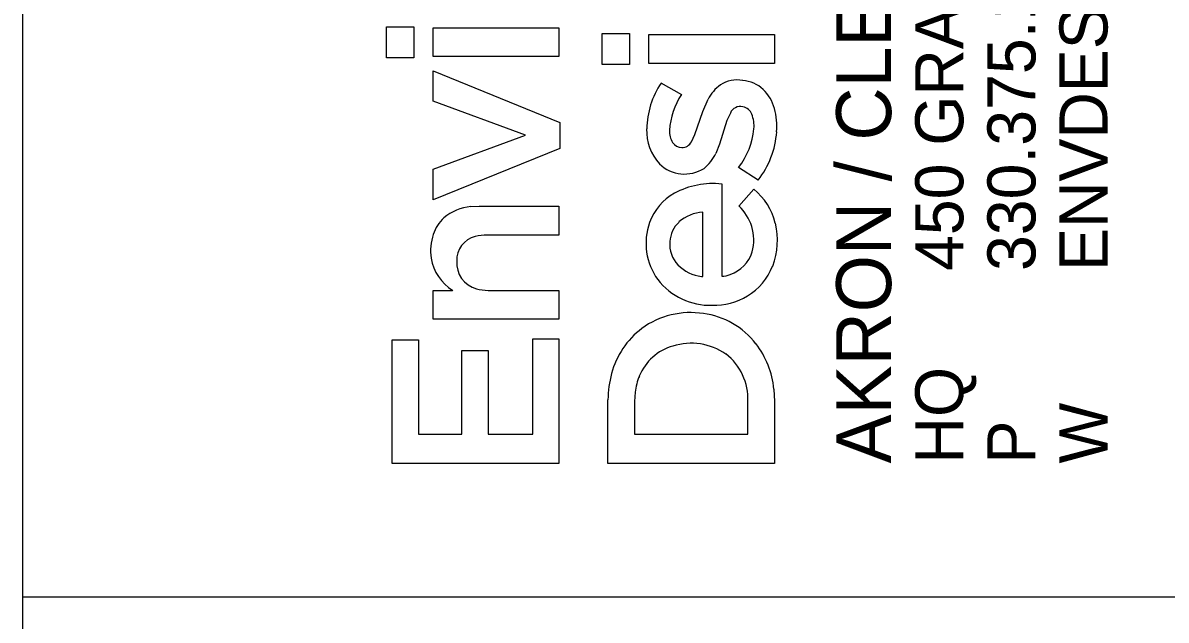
# Model space of a CAD drawing. Extents: x -0.4 to 34, y 0 to 22.
# Drawn here: x 32 to 33.185, y 2.476 to 3.094 of the extents above; entities that cross this region are included whole.
import ezdxf

# ---------------------------------------------------------------- set-up
doc = ezdxf.new("R2010")
doc.units = 0
doc.layers.add('SH_Border', color=7, linetype='Continuous')
doc.layers.add('SH_Data', color=7, linetype='Continuous')

msp = doc.modelspace()

# ---------------------------------------------------------------- linework, layer by layer
at = {"layer": 'SH_Border'}
for p, q in [((32, 0.5), (32, 21.5)), ((32, 2.5), (33.5, 2.5))]:
    msp.add_line(p, q, dxfattribs=at)
at = {"layer": 'SH_Data'}
for p, q in [((32.3771, 3.0582), (32.3771, 3.0903)), ((32.3771, 3.0903), (32.4054, 3.0903)), ((32.4054, 3.0903), (32.4054, 3.0582)), ((32.4254, 3.0594), (32.4254, 3.0893)), ((32.4254, 3.0893), (32.5557, 3.0893)), ((32.5557, 3.0893), (32.5557, 3.0594)), ((32.6005, 3.0511), (32.6005, 3.0832)), ((32.6005, 3.0832), (32.6289, 3.0832)), ((32.6289, 3.0832), (32.6289, 3.0511)), ((32.6489, 3.0523), (32.6489, 3.0822)), ((32.6489, 3.0822), (32.7792, 3.0822)), ((32.7792, 3.0822), (32.7792, 3.0523)), ((32.4054, 3.0582), (32.3771, 3.0582)), ((32.5557, 3.0594), (32.4254, 3.0594)), ((32.6289, 3.0511), (32.6005, 3.0511)), ((32.7792, 3.0523), (32.6489, 3.0523)), ((32.4254, 3.0133), (32.4254, 3.0446)), ((32.4254, 3.0446), (32.5567, 2.9913)), ((32.6615, 3.0321), (32.6827, 3.0203)), ((32.5212, 2.978), (32.4254, 3.0133)), ((32.7048, 3.0026), (32.7104, 3.0153)), ((32.6967, 2.9787), (32.7048, 3.0026)), ((32.7334, 3.001), (32.7298, 2.9933)), ((32.5567, 2.9913), (32.5567, 2.9644)), ((32.7298, 2.9933), (32.7221, 2.9688)), ((32.4254, 2.9429), (32.5212, 2.978)), ((32.693, 2.9712), (32.6967, 2.9787)), ((32.5567, 2.9644), (32.4254, 2.9109)), ((32.7221, 2.9688), (32.7182, 2.9592)), ((32.4254, 2.9109), (32.4254, 2.9429)), ((32.7621, 2.9314), (32.742, 2.9447)), ((32.7245, 2.9275), (32.7246, 2.8319)), ((32.7423, 2.9046), (32.7577, 2.922)), ((32.4644, 2.904), (32.4729, 2.9044)), ((32.4729, 2.9044), (32.5557, 2.9044)), ((32.5557, 2.9044), (32.5557, 2.8746)), ((32.7049, 2.8318), (32.7049, 2.8983)), ((32.5557, 2.8746), (32.4814, 2.8746)), ((32.7036, 2.8317), (32.7049, 2.8318)), ((32.4254, 2.7875), (32.4254, 2.8173)), ((32.4254, 2.8173), (32.4455, 2.8173)), ((32.4822, 2.8173), (32.5557, 2.8173)), ((32.5557, 2.8173), (32.5557, 2.7876)), ((32.5557, 2.7876), (32.4254, 2.7875)), ((32.383, 2.6379), (32.383, 2.766)), ((32.383, 2.766), (32.4101, 2.766)), ((32.4101, 2.766), (32.4101, 2.6683)), ((32.5286, 2.6683), (32.5286, 2.7672)), ((32.5286, 2.7672), (32.5557, 2.7672)), ((32.5557, 2.7672), (32.5557, 2.6379)), ((32.455, 2.6683), (32.455, 2.7549)), ((32.455, 2.7549), (32.4822, 2.7549)), ((32.4822, 2.7549), (32.4822, 2.6683)), ((32.7785, 2.715), (32.7792, 2.7021)), ((32.6064, 2.638), (32.6064, 2.704)), ((32.6347, 2.7118), (32.6341, 2.7023)), ((32.6341, 2.7023), (32.6341, 2.6684)), ((32.7515, 2.6683), (32.7515, 2.7024)), ((32.7792, 2.7021), (32.7792, 2.638)), ((32.4101, 2.6683), (32.455, 2.6683)), ((32.4822, 2.6683), (32.5286, 2.6683)), ((32.6341, 2.6684), (32.7515, 2.6683)), ((32.5557, 2.6379), (32.383, 2.6379)), ((32.7792, 2.638), (32.6064, 2.638))]:
    msp.add_line(p, q, dxfattribs=at)
for points in [[(32.3771, 3.0582), (32.3771, 3.0903), (32.4054, 3.0903), (32.4054, 3.0582)], [(32.4254, 3.0594), (32.4254, 3.0893), (32.5557, 3.0893), (32.5557, 3.0594)], [(32.6005, 3.0511), (32.6005, 3.0832), (32.6289, 3.0832), (32.6289, 3.0511)], [(32.6489, 3.0523), (32.6489, 3.0822), (32.7792, 3.0822), (32.7792, 3.0523)], [(32.4254, 2.9109), (32.4254, 2.9429), (32.5212, 2.978), (32.4254, 3.0133), (32.4254, 3.0446), (32.5567, 2.9913), (32.5567, 2.9644)], [(32.383, 2.6379), (32.383, 2.766), (32.4101, 2.766), (32.4101, 2.6683), (32.455, 2.6683), (32.455, 2.7549), (32.4822, 2.7549), (32.4822, 2.6683), (32.5286, 2.6683), (32.5286, 2.7672), (32.5557, 2.7672), (32.5557, 2.6379)]]:
    msp.add_lwpolyline(points, close=True, dxfattribs=at)
for points in [[(32.6615, 3.0321), (32.6827, 3.0203)], [(32.693, 2.9712), (32.6967, 2.9787), (32.7048, 3.0026), (32.7104, 3.0153)], [(32.7334, 3.001), (32.7298, 2.9933), (32.7221, 2.9688), (32.7182, 2.9592)], [(32.7621, 2.9314), (32.742, 2.9447)], [(32.7245, 2.9275), (32.7246, 2.8319)], [(32.7423, 2.9046), (32.7577, 2.922)], [(32.4644, 2.904), (32.4729, 2.9044), (32.5557, 2.9044), (32.5557, 2.8746), (32.4814, 2.8746)], [(32.7036, 2.8317), (32.7049, 2.8318), (32.7049, 2.8983)], [(32.4254, 2.7875), (32.4254, 2.8173), (32.4455, 2.8173)], [(32.4822, 2.8173), (32.5557, 2.8173), (32.5557, 2.7876), (32.4254, 2.7875)], [(32.7785, 2.715), (32.7792, 2.7021), (32.7792, 2.638), (32.6064, 2.638)], [(32.6064, 2.638), (32.6064, 2.704)], [(32.6347, 2.7118), (32.6341, 2.7023), (32.6341, 2.6684), (32.7515, 2.6683), (32.7515, 2.7024)]]:
    msp.add_lwpolyline(points, dxfattribs=at)
for centre, radius, start, end in [((32.7406, 3.0026), 0.0326, 80.1719, 122.5197), ((32.7406, 3.0026), 0.0326, 80.1719, 122.5197), ((32.7428, 2.9982), 0.0367, 47.7934, 84.6892), ((32.7428, 2.9982), 0.0367, 47.7934, 84.6892), ((32.7364, 2.9826), 0.0897, 146.531, 178.7571), ((32.7364, 2.9826), 0.0897, 146.531, 178.7571), ((32.7466, 2.9971), 0.0405, 125.5118, 153.4159), ((32.7466, 2.9971), 0.0405, 125.5118, 153.4159), ((32.7379, 2.9946), 0.0427, 14.9966, 46.2063), ((32.7379, 2.9946), 0.0427, 14.9966, 46.2063), ((32.7452, 2.9789), 0.0749, 146.5112, 176.9101), ((32.7452, 2.9789), 0.0749, 146.5112, 176.9101), ((32.7438, 2.9963), 0.0114, 76.6609, 155.7053), ((32.7438, 2.9963), 0.0114, 76.6609, 155.7053), ((32.744, 2.9951), 0.0126, 21.5098, 78.5262), ((32.744, 2.9951), 0.0126, 21.5098, 78.5262), ((32.7259, 2.9877), 0.0321, 354.5726, 22.068), ((32.7259, 2.9877), 0.0321, 354.5726, 22.068), ((32.7104, 2.9867), 0.0712, 355.8306, 15.3914), ((32.7104, 2.9867), 0.0712, 355.8306, 15.3914), ((32.6967, 2.9824), 0.0501, 177.5366, 222.7932), ((32.6967, 2.9824), 0.0501, 177.5366, 222.7932), ((32.6931, 2.9823), 0.0228, 178.4747, 211.0868), ((32.6931, 2.9823), 0.0228, 178.4747, 211.0868), ((32.6825, 2.9915), 0.0757, 321.811, 354.7969), ((32.6825, 2.9915), 0.0757, 321.811, 354.7969), ((32.6895, 2.9882), 0.0922, 321.9777, 355.8738), ((32.6895, 2.9882), 0.0922, 321.9777, 355.8738), ((32.6833, 2.9767), 0.0115, 212.2368, 268.3777), ((32.6833, 2.9767), 0.0115, 212.2368, 268.3777), ((32.6834, 2.9759), 0.0107, 267.716, 333.7337), ((32.6834, 2.9759), 0.0107, 267.716, 333.7337), ((32.681, 2.9758), 0.0408, 308.0877, 335.9874), ((32.681, 2.9758), 0.0408, 308.0877, 335.9874), ((32.686, 2.9753), 0.0375, 225.9854, 302.4797), ((32.686, 2.9753), 0.0375, 225.9854, 302.4797), ((32.7152, 2.8441), 0.0838, 83.615, 118.2876), ((32.7152, 2.8441), 0.0838, 83.615, 118.2876), ((32.7024, 2.8691), 0.0558, 118.8308, 160.6244), ((32.7024, 2.8691), 0.0558, 118.8308, 160.6244), ((32.7174, 2.8717), 0.0644, 13.5336, 51.3615), ((32.7174, 2.8717), 0.0644, 13.5336, 51.3615), ((32.4687, 2.8543), 0.0499, 94.9696, 130.2225), ((32.4687, 2.8543), 0.0499, 94.9696, 130.2225), ((32.7038, 2.8656), 0.0549, 19.0357, 45.4406), ((32.7038, 2.8656), 0.0549, 19.0357, 45.4406), ((32.4635, 2.8626), 0.0402, 132.2219, 161.6818), ((32.4635, 2.8626), 0.0402, 132.2219, 161.6818), ((32.7079, 2.8561), 0.0424, 94.008, 130.8817), ((32.7079, 2.8561), 0.0424, 94.008, 130.8817), ((32.7104, 2.8661), 0.0644, 160.5201, 215.7831), ((32.7104, 2.8661), 0.0644, 160.5201, 215.7831), ((32.7005, 2.8663), 0.0298, 132.9851, 177.179), ((32.7005, 2.8663), 0.0298, 132.9851, 177.179), ((32.7107, 2.8697), 0.047, 344.6059, 17.007), ((32.7107, 2.8697), 0.047, 344.6059, 17.007), ((32.7064, 2.8692), 0.0758, 339.3542, 13.3785), ((32.7064, 2.8692), 0.0758, 339.3542, 13.3785), ((32.4787, 2.8582), 0.056, 162.2736, 187.7919), ((32.4787, 2.8582), 0.056, 162.2736, 187.7919), ((32.4748, 2.8487), 0.025, 103.6865, 182.2187), ((32.4748, 2.8487), 0.025, 103.6865, 182.2187), ((32.4811, 2.8286), 0.046, 89.6049, 105.3284), ((32.4811, 2.8286), 0.046, 89.6049, 105.3284), ((32.7017, 2.865), 0.0311, 175.0013, 223.283), ((32.7017, 2.865), 0.0311, 175.0013, 223.283), ((32.7224, 2.8671), 0.035, 288.0077, 343.5508), ((32.7224, 2.8671), 0.035, 288.0077, 343.5508), ((32.4703, 2.858), 0.0476, 188.962, 238.7037), ((32.4703, 2.858), 0.0476, 188.962, 238.7037), ((32.4773, 2.8456), 0.0276, 175.5854, 255.1439), ((32.4773, 2.8456), 0.0276, 175.5854, 255.1439), ((32.7089, 2.8736), 0.0423, 225.0619, 262.7974), ((32.7089, 2.8736), 0.0423, 225.0619, 262.7974), ((32.7247, 2.8522), 0.0202, 269.7003, 294.8711), ((32.7247, 2.8522), 0.0202, 269.7003, 294.8711), ((32.7189, 2.8652), 0.0626, 300.9427, 338.7323), ((32.7189, 2.8652), 0.0626, 300.9427, 338.7323), ((32.7125, 2.8705), 0.0687, 217.7452, 271.6543), ((32.7125, 2.8705), 0.0687, 217.7452, 271.6543), ((32.4818, 2.8595), 0.0422, 254.0916, 270.5284), ((32.4818, 2.8595), 0.0422, 254.0916, 270.5284), ((32.7155, 2.8724), 0.0706, 269.2048, 300.3341), ((32.7155, 2.8724), 0.0706, 269.2048, 300.3341), ((32.6923, 2.7079), 0.0864, 81.194, 125.9984), ((32.6923, 2.7079), 0.0864, 81.194, 125.9984), ((32.6946, 2.7113), 0.0827, 37.8521, 82.402), ((32.6946, 2.7113), 0.0827, 37.8521, 82.402), ((32.6939, 2.7089), 0.0865, 127.2362, 165.148), ((32.6939, 2.7089), 0.0865, 127.2362, 165.148), ((32.6928, 2.6986), 0.0639, 55.6727, 107.2093), ((32.6928, 2.6986), 0.0639, 55.6727, 107.2093), ((32.6859, 2.7057), 0.0931, 5.7333, 37.304), ((32.6859, 2.7057), 0.0931, 5.7333, 37.304), ((32.6889, 2.7078), 0.054, 106.1881, 157.3861), ((32.6889, 2.7078), 0.054, 106.1881, 157.3861), ((32.6929, 2.705), 0.0587, 357.4662, 52.2665), ((32.6929, 2.705), 0.0587, 357.4662, 52.2665), ((32.7143, 2.7028), 0.1078, 164.7861, 179.3704), ((32.7143, 2.7028), 0.1078, 164.7861, 179.3704), ((32.6983, 2.7039), 0.0641, 157.3571, 172.9275), ((32.6983, 2.7039), 0.0641, 157.3571, 172.9275)]:
    msp.add_arc(centre, radius, start, end, dxfattribs=at)

# ---------------------------------------------------------------- texts
for s, height, p in [('450 GRANT ST., AKRON, OH  44311', 0.049846, (32.9749, 2.8374)), ('AKRON / CLEVELAND / COLUMBUS', 0.056969, (32.9001, 2.638)), ('ENVDESIGNGROUP.COM', 0.049846, (33.1244, 2.8374)), ('330.375.1390', 0.049846, (33.0497, 2.8374)), ('HQ ', 0.04985, (32.9749, 2.638)), ('W', 0.0498, (33.1244, 2.638)), ('P', 0.0498, (33.0497, 2.638))]:
    msp.add_text(s, height=height, rotation=90, dxfattribs=at).set_placement(p)

doc.saveas('drawing.dxf')
